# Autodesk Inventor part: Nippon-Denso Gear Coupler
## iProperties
Shininess: 64.0
Length Units: 11272
Angle Units: 11279
Time Units: 11290
Mass Units: 11286
Length Display Precision: 3
Angle Display Precision: 2
Category: FIRST Robotics Components
Manager: Ed Sparks
Company: FIRST CAD Library
Created: 2003-01
Part Number: Nippon-Denso Gear Coupler
Project: FIRST
Material: ABS Plastic
Document SubType Name: Modeling
Designer: Administrator
Engineer: Ed Sparks
Density: 1 g/cm^3
Density: 0.0
Volumn: 0.0
Area: 0.0
PropertySet Name: Model Information
Control State: 0
Master: False
Checked Out: False
Subject: Robot Component
Author: Administrator
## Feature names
1. Extrusion1
2. Mounting Hole [Hole]
3. Circular Pattern1
4. Extrusion2
5. Hole3
6. Extrusion3
7. Circular Pattern2
8. Fillet1
